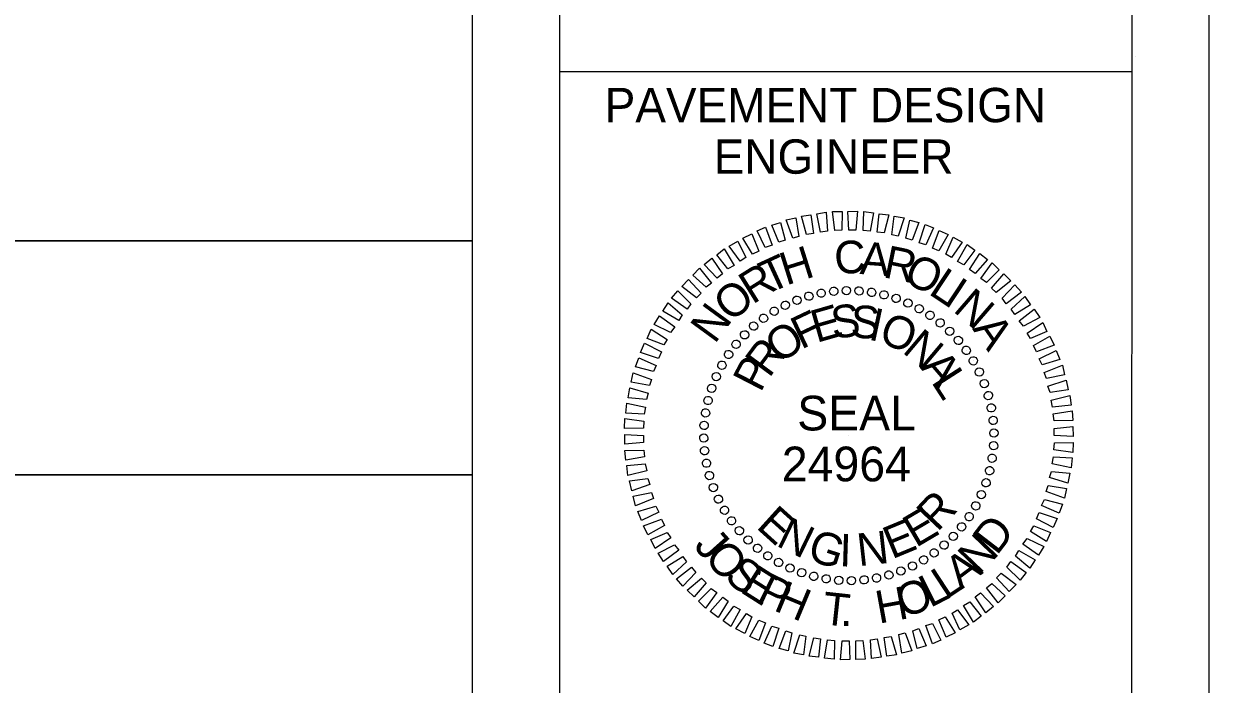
# Model space of a CAD drawing. Extents: x 1553884 to 1554215, y 810431 to 810779.
# Drawn here: x 1554125.27 to 1554156.35, y 810737.21 to 810754.53 of the extents above; entities that cross this region are included whole.
import ezdxf

# ---------------------------------------------------------------- set-up
doc = ezdxf.new("R2010")
doc.units = 0
for name, color, linetype in [('Exist Structure Minor Drop Inlet Top Elevation', 7, 'Continuous'), ('Old_Level_2', 7, 'Continuous'), ('Prop Dimension', 7, 'Continuous'), ('Prop Lane Arrow CELL', 7, 'Continuous'), ('Typical Arrow Superelevation CELL', 7, 'Continuous')]:
    doc.layers.add(name, color=color, linetype=linetype)

msp = doc.modelspace()

# ---------------------------------------------------------------- linework, layer by layer
at = {"layer": 'Exist Structure Minor Drop Inlet Top Elevation'}
for p, q in [((1554154.423, 810753.681), (1554154.423, 810753.681)), ((1554145.537, 810747.289), (1554145.537, 810747.289)), ((1554145.853, 810747.393), (1554145.853, 810747.393)), ((1554146.178, 810747.467), (1554146.178, 810747.467)), ((1554146.503, 810747.518), (1554146.503, 810747.518)), ((1554146.837, 810747.539), (1554146.837, 810747.539)), ((1554147.171, 810747.53), (1554147.171, 810747.53)), ((1554147.497, 810747.49), (1554147.497, 810747.49)), ((1554147.824, 810747.427), (1554147.824, 810747.427)), ((1554148.144, 810747.335), (1554148.144, 810747.335)), ((1554144.943, 810746.998), (1554144.943, 810746.998)), ((1554145.236, 810747.155), (1554145.236, 810747.155)), ((1554148.45, 810747.211), (1554148.45, 810747.211)), ((1554148.748, 810747.065), (1554148.748, 810747.065)), ((1554144.665, 810746.811), (1554144.665, 810746.811)), ((1554149.032, 810746.887), (1554149.032, 810746.887)), ((1554149.301, 810746.695), (1554149.301, 810746.695)), ((1554144.165, 810746.378), (1554144.165, 810746.378)), ((1554144.403, 810746.61), (1554144.403, 810746.61)), ((1554149.547, 810746.472), (1554149.547, 810746.472)), ((1554143.942, 810746.131), (1554143.942, 810746.131)), ((1554149.779, 810746.233), (1554149.779, 810746.233)), ((1554143.749, 810745.862), (1554143.749, 810745.862)), ((1554149.981, 810745.971), (1554149.981, 810745.971)), ((1554143.572, 810745.579), (1554143.572, 810745.579)), ((1554150.168, 810745.694), (1554150.168, 810745.694)), ((1554143.426, 810745.28), (1554143.426, 810745.28)), ((1554150.324, 810745.401), (1554150.324, 810745.401)), ((1554143.302, 810744.975), (1554143.302, 810744.975)), ((1554150.459, 810745.1), (1554150.459, 810745.1)), ((1554143.209, 810744.655), (1554143.209, 810744.655)), ((1554150.563, 810744.783), (1554150.563, 810744.783)), ((1554143.146, 810744.328), (1554143.146, 810744.328)), ((1554150.637, 810744.458), (1554150.637, 810744.458)), ((1554143.107, 810744.001), (1554143.107, 810744.001)), ((1554150.688, 810744.133), (1554150.688, 810744.133)), ((1554143.097, 810743.667), (1554143.097, 810743.667)), ((1554146.903, 810743.733), (1554146.903, 810743.733)), ((1554150.709, 810743.8), (1554150.709, 810743.8)), ((1554143.118, 810743.334), (1554143.118, 810743.334)), ((1554150.699, 810743.466), (1554150.699, 810743.466)), ((1554143.17, 810743.008), (1554143.17, 810743.008)), ((1554150.66, 810743.139), (1554150.66, 810743.139)), ((1554143.243, 810742.684), (1554143.243, 810742.684)), ((1554150.597, 810742.812), (1554150.597, 810742.812)), ((1554143.348, 810742.367), (1554143.348, 810742.367)), ((1554150.504, 810742.492), (1554150.504, 810742.492)), ((1554143.482, 810742.066), (1554143.482, 810742.066)), ((1554150.38, 810742.186), (1554150.38, 810742.186)), ((1554143.639, 810741.773), (1554143.639, 810741.773)), ((1554150.234, 810741.888), (1554150.234, 810741.888)), ((1554143.825, 810741.496), (1554143.825, 810741.496)), ((1554150.057, 810741.605), (1554150.057, 810741.605)), ((1554144.027, 810741.234), (1554144.027, 810741.234)), ((1554149.641, 810741.089), (1554149.641, 810741.089)), ((1554149.865, 810741.336), (1554149.865, 810741.336)), ((1554144.259, 810740.995), (1554144.259, 810740.995)), ((1554144.505, 810740.772), (1554144.505, 810740.772)), ((1554149.403, 810740.857), (1554149.403, 810740.857)), ((1554144.774, 810740.58), (1554144.774, 810740.58)), ((1554148.864, 810740.469), (1554148.864, 810740.469)), ((1554149.141, 810740.656), (1554149.141, 810740.656)), ((1554145.058, 810740.402), (1554145.058, 810740.402)), ((1554145.356, 810740.256), (1554145.356, 810740.256)), ((1554145.662, 810740.132), (1554145.662, 810740.132)), ((1554148.269, 810740.178), (1554148.269, 810740.178)), ((1554148.571, 810740.312), (1554148.571, 810740.312)), ((1554145.982, 810740.039), (1554145.982, 810740.039)), ((1554146.309, 810739.977), (1554146.309, 810739.977)), ((1554146.636, 810739.937), (1554146.636, 810739.937)), ((1554146.969, 810739.928), (1554146.969, 810739.928)), ((1554147.303, 810739.949), (1554147.303, 810739.949)), ((1554147.628, 810740), (1554147.628, 810740)), ((1554147.953, 810740.074), (1554147.953, 810740.074))]:
    msp.add_line(p, q, dxfattribs=at)
for points in [[(1554145.795, 810749.007), (1554145.658, 810749.483), (1554145.907, 810749.517), (1554145.976, 810749.033)], [(1554146.158, 810749.067), (1554146.058, 810749.543), (1554146.308, 810749.585), (1554146.339, 810749.093)], [(1554146.536, 810749.111), (1554146.475, 810749.603), (1554146.725, 810749.607), (1554146.718, 810749.114)], [(1554146.9, 810749.118), (1554146.876, 810749.61), (1554147.126, 810749.614), (1554147.082, 810749.121)], [(1554147.279, 810749.109), (1554147.293, 810749.602), (1554147.544, 810749.569), (1554147.462, 810749.089)], [(1554147.644, 810749.062), (1554147.696, 810749.549), (1554147.947, 810749.523), (1554147.827, 810749.043)], [(1554148.032, 810748.993), (1554148.092, 810749.487), (1554148.351, 810749.439), (1554148.192, 810748.958)], [(1554144.709, 810748.662), (1554144.496, 810749.098), (1554144.715, 810749.193), (1554144.89, 810748.719)], [(1554145.07, 810748.798), (1554144.881, 810749.249), (1554145.114, 810749.322), (1554145.229, 810748.853)], [(1554145.432, 810748.91), (1554145.257, 810749.385), (1554145.514, 810749.442), (1554145.591, 810748.951)], [(1554148.398, 810748.909), (1554148.496, 810749.381), (1554148.732, 810749.316), (1554148.558, 810748.858)], [(1554148.741, 810748.786), (1554148.899, 810749.266), (1554149.121, 810749.179), (1554148.924, 810748.736)], [(1554144.055, 810748.302), (1554143.76, 810748.699), (1554143.993, 810748.832), (1554144.198, 810748.396)], [(1554144.378, 810748.49), (1554144.121, 810748.91), (1554144.354, 810749.02), (1554144.544, 810748.568)], [(1554149.092, 810748.648), (1554149.266, 810749.106), (1554149.503, 810749.004), (1554149.26, 810748.575)], [(1554149.444, 810748.487), (1554149.633, 810748.93), (1554149.871, 810748.805), (1554149.59, 810748.399)], [(1554143.733, 810748.099), (1554143.438, 810748.473), (1554143.633, 810748.628), (1554143.898, 810748.193)], [(1554149.751, 810748.295), (1554150.001, 810748.739), (1554150.201, 810748.591), (1554149.919, 810748.207)], [(1554143.449, 810747.859), (1554143.109, 810748.217), (1554143.311, 810748.38), (1554143.591, 810747.968)], [(1554150.065, 810748.081), (1554150.331, 810748.503), (1554150.538, 810748.347), (1554150.211, 810747.977)], [(1554150.365, 810747.851), (1554150.661, 810748.258), (1554150.846, 810748.079), (1554150.511, 810747.747)], [(1554143.157, 810747.619), (1554142.81, 810747.939), (1554142.989, 810748.124), (1554143.299, 810747.728)], [(1554150.643, 810747.598), (1554150.962, 810747.968), (1554151.147, 810747.789), (1554150.766, 810747.479)], [(1554142.912, 810747.342), (1554142.52, 810747.638), (1554142.699, 810747.823), (1554143.031, 810747.465)], [(1554150.92, 810747.33), (1554151.255, 810747.684), (1554151.425, 810747.49), (1554151.029, 810747.188)], [(1554142.659, 810747.042), (1554142.252, 810747.33), (1554142.416, 810747.53), (1554142.763, 810747.187)], [(1554151.16, 810747.046), (1554151.518, 810747.378), (1554151.666, 810747.161), (1554151.254, 810746.903)], [(1554142.444, 810746.75), (1554142.023, 810746.993), (1554142.163, 810747.215), (1554142.533, 810746.895)], [(1554151.363, 810746.739), (1554151.759, 810747.041), (1554151.907, 810746.824), (1554151.479, 810746.597)], [(1554142.23, 810746.435), (1554141.794, 810746.647), (1554141.934, 810746.87), (1554142.341, 810746.581)], [(1554151.573, 810746.416), (1554151.985, 810746.696), (1554152.095, 810746.463), (1554151.667, 810746.274)], [(1554142.054, 810746.106), (1554141.618, 810746.28), (1554141.72, 810746.517), (1554142.142, 810746.251)], [(1554141.916, 810745.755), (1554141.443, 810745.913), (1554141.545, 810746.15), (1554141.989, 810745.923)], [(1554151.738, 810746.093), (1554152.174, 810746.336), (1554152.284, 810746.102), (1554151.817, 810745.927)], [(1554141.778, 810745.411), (1554141.305, 810745.532), (1554141.392, 810745.768), (1554141.851, 810745.571)], [(1554151.888, 810745.747), (1554152.339, 810745.959), (1554152.435, 810745.726), (1554151.967, 810745.589)], [(1554152.023, 810745.385), (1554152.498, 810745.575), (1554152.555, 810745.326), (1554152.079, 810745.227)], [(1554141.678, 810745.045), (1554141.199, 810745.128), (1554141.247, 810745.379), (1554141.728, 810745.205)], [(1554152.121, 810745.023), (1554152.596, 810745.183), (1554152.653, 810744.926), (1554152.176, 810744.864)], [(1554141.593, 810744.68), (1554141.115, 810744.724), (1554141.163, 810744.983), (1554141.644, 810744.84)], [(1554141.539, 810744.292), (1554141.054, 810744.321), (1554141.079, 810744.58), (1554141.574, 810744.475)], [(1554152.203, 810744.66), (1554152.694, 810744.782), (1554152.728, 810744.525), (1554152.244, 810744.479)], [(1554141.515, 810743.927), (1554141.023, 810743.919), (1554141.033, 810744.177), (1554141.527, 810744.11)], [(1554152.262, 810744.297), (1554152.754, 810744.382), (1554152.773, 810744.124), (1554152.281, 810744.116)], [(1554152.284, 810743.918), (1554152.776, 810743.965), (1554152.781, 810743.707), (1554152.287, 810743.736)], [(1554141.522, 810743.548), (1554141.03, 810743.502), (1554141.025, 810743.76), (1554141.519, 810743.731)], [(1554141.544, 810743.17), (1554141.052, 810743.085), (1554141.033, 810743.343), (1554141.525, 810743.351)], [(1554152.291, 810743.539), (1554152.783, 810743.548), (1554152.773, 810743.29), (1554152.279, 810743.357)], [(1554141.603, 810742.807), (1554141.112, 810742.684), (1554141.078, 810742.942), (1554141.562, 810742.988)], [(1554152.267, 810743.175), (1554152.753, 810743.145), (1554152.727, 810742.887), (1554152.232, 810742.992)], [(1554152.213, 810742.787), (1554152.691, 810742.742), (1554152.643, 810742.484), (1554152.163, 810742.627)], [(1554141.685, 810742.444), (1554141.21, 810742.284), (1554141.153, 810742.541), (1554141.63, 810742.602)], [(1554152.128, 810742.422), (1554152.607, 810742.339), (1554152.559, 810742.088), (1554152.078, 810742.262)], [(1554141.783, 810742.082), (1554141.308, 810741.892), (1554141.251, 810742.141), (1554141.727, 810742.24)], [(1554152.028, 810742.056), (1554152.501, 810741.935), (1554152.414, 810741.699), (1554151.955, 810741.895)], [(1554141.918, 810741.72), (1554141.467, 810741.508), (1554141.372, 810741.741), (1554141.839, 810741.878)], [(1554151.89, 810741.712), (1554152.363, 810741.554), (1554152.261, 810741.317), (1554151.817, 810741.544)], [(1554142.068, 810741.374), (1554141.632, 810741.131), (1554141.522, 810741.365), (1554141.989, 810741.539)], [(1554142.233, 810741.051), (1554141.821, 810740.771), (1554141.711, 810741.004), (1554142.139, 810741.193)], [(1554151.752, 810741.361), (1554152.188, 810741.187), (1554152.086, 810740.95), (1554151.664, 810741.216)], [(1554142.443, 810740.728), (1554142.047, 810740.426), (1554141.899, 810740.643), (1554142.327, 810740.87)], [(1554151.576, 810741.032), (1554152.012, 810740.82), (1554151.872, 810740.597), (1554151.465, 810740.886)], [(1554142.646, 810740.421), (1554142.288, 810740.089), (1554142.14, 810740.306), (1554142.552, 810740.564)], [(1554151.362, 810740.717), (1554151.783, 810740.474), (1554151.643, 810740.252), (1554151.273, 810740.572)], [(1554142.886, 810740.137), (1554142.551, 810739.782), (1554142.38, 810739.976), (1554142.777, 810740.279)], [(1554151.147, 810740.425), (1554151.554, 810740.137), (1554151.39, 810739.937), (1554151.043, 810740.279)], [(1554143.164, 810739.869), (1554142.844, 810739.499), (1554142.659, 810739.678), (1554143.04, 810739.988)], [(1554150.649, 810739.848), (1554150.996, 810739.528), (1554150.817, 810739.343), (1554150.507, 810739.739)], [(1554150.894, 810740.125), (1554151.286, 810739.829), (1554151.107, 810739.644), (1554150.775, 810740.002)], [(1554143.441, 810739.616), (1554143.145, 810739.209), (1554142.96, 810739.388), (1554143.295, 810739.719)], [(1554150.357, 810739.608), (1554150.697, 810739.25), (1554150.495, 810739.087), (1554150.215, 810739.499)], [(1554143.741, 810739.386), (1554143.475, 810738.964), (1554143.268, 810739.12), (1554143.595, 810739.49)], [(1554144.056, 810739.172), (1554143.805, 810738.727), (1554143.606, 810738.876), (1554143.887, 810739.26)], [(1554150.073, 810739.368), (1554150.368, 810738.994), (1554150.173, 810738.839), (1554149.908, 810739.274)], [(1554144.362, 810738.98), (1554144.173, 810738.537), (1554143.935, 810738.661), (1554144.217, 810739.068)], [(1554144.714, 810738.819), (1554144.54, 810738.361), (1554144.303, 810738.463), (1554144.546, 810738.892)], [(1554149.428, 810738.977), (1554149.685, 810738.557), (1554149.452, 810738.447), (1554149.262, 810738.899)], [(1554149.751, 810739.165), (1554150.046, 810738.768), (1554149.813, 810738.635), (1554149.608, 810739.071)], [(1554145.065, 810738.681), (1554144.907, 810738.201), (1554144.685, 810738.288), (1554144.882, 810738.731)], [(1554145.408, 810738.558), (1554145.311, 810738.086), (1554145.074, 810738.15), (1554145.248, 810738.608)], [(1554148.736, 810738.669), (1554148.925, 810738.218), (1554148.692, 810738.145), (1554148.577, 810738.613)], [(1554149.097, 810738.805), (1554149.31, 810738.369), (1554149.091, 810738.274), (1554148.916, 810738.748)], [(1554145.774, 810738.474), (1554145.714, 810737.98), (1554145.456, 810738.028), (1554145.614, 810738.509)], [(1554146.162, 810738.405), (1554146.11, 810737.918), (1554145.859, 810737.944), (1554145.98, 810738.424)], [(1554146.527, 810738.358), (1554146.513, 810737.865), (1554146.262, 810737.898), (1554146.344, 810738.377)], [(1554146.906, 810738.349), (1554146.93, 810737.857), (1554146.68, 810737.852), (1554146.724, 810738.346)], [(1554147.27, 810738.356), (1554147.331, 810737.864), (1554147.081, 810737.859), (1554147.088, 810738.352)], [(1554147.648, 810738.4), (1554147.748, 810737.924), (1554147.498, 810737.882), (1554147.467, 810738.374)], [(1554148.011, 810738.459), (1554148.148, 810737.984), (1554147.899, 810737.95), (1554147.83, 810738.434)], [(1554148.374, 810738.557), (1554148.549, 810738.082), (1554148.292, 810738.025), (1554148.215, 810738.516)]]:
    msp.add_lwpolyline(points, close=True, dxfattribs=at)
for centre, major_axis in [((1554146.505, 810747.513), (-0.011, 0.109)), ((1554146.836, 810747.533), (-0.002, 0.109)), ((1554147.168, 810747.524), (0.008, 0.109)), ((1554147.497, 810747.487), (0.017, 0.108)), ((1554145.54, 810747.281), (-0.039, 0.102)), ((1554145.854, 810747.386), (-0.03, 0.105)), ((1554146.177, 810747.464), (-0.021, 0.107)), ((1554147.823, 810747.421), (0.026, 0.106)), ((1554148.141, 810747.327), (0.036, 0.103)), ((1554148.449, 810747.205), (0.0444, 0.0997)), ((1554144.944, 810746.991), (-0.0562, 0.0936)), ((1554145.235, 810747.149), (-0.0479, 0.0981)), ((1554148.746, 810747.057), (0.0529, 0.0955)), ((1554149.029, 810746.884), (0.0611, 0.0905)), ((1554144.407, 810746.601), (-0.0716, 0.0824)), ((1554144.667, 810746.807), (-0.0642, 0.0883)), ((1554149.296, 810746.686), (0.0687, 0.0849)), ((1554144.167, 810746.372), (-0.0785, 0.0758)), ((1554149.544, 810746.466), (0.0758, 0.0785)), ((1554149.773, 810746.226), (0.0824, 0.0716)), ((1554143.947, 810746.124), (-0.0849, 0.0687)), ((1554149.979, 810745.966), (0.0883, 0.0642)), ((1554143.749, 810745.857), (-0.0905, 0.0611)), ((1554150.163, 810745.689), (0.0936, 0.0562)), ((1554143.576, 810745.574), (-0.0955, 0.0529)), ((1554150.321, 810745.398), (0.0981, 0.0479)), ((1554143.428, 810745.277), (-0.0997, 0.0444)), ((1554150.453, 810745.093), (0.102, 0.039)), ((1554143.306, 810744.969), (-0.103, 0.036)), ((1554150.558, 810744.779), (0.105, 0.03)), ((1554143.212, 810744.651), (-0.106, 0.026)), ((1554150.636, 810744.456), (0.107, 0.021)), ((1554143.146, 810744.325), (-0.108, 0.017)), ((1554150.685, 810744.128), (0.109, 0.011)), ((1554143.108, 810743.996), (-0.109, 0.008)), ((1554150.705, 810743.797), (0.109, 0.002)), ((1554143.1, 810743.664), (-0.109, -0.002)), ((1554150.697, 810743.465), (0.109, -0.008)), ((1554143.12, 810743.333), (-0.109, -0.011)), ((1554150.659, 810743.136), (0.108, -0.017)), ((1554143.169, 810743.005), (-0.107, -0.021)), ((1554150.593, 810742.81), (0.106, -0.026)), ((1554143.247, 810742.682), (-0.105, -0.03)), ((1554143.352, 810742.367), (-0.102, -0.039)), ((1554150.377, 810742.184), (0.0997, -0.0444)), ((1554150.499, 810742.492), (0.103, -0.036)), ((1554143.484, 810742.063), (-0.0981, -0.0479)), ((1554150.229, 810741.887), (0.0955, -0.0529)), ((1554143.642, 810741.772), (-0.0936, -0.0562)), ((1554150.056, 810741.604), (0.0905, -0.0611)), ((1554143.826, 810741.495), (-0.0883, -0.0642)), ((1554149.858, 810741.337), (0.0849, -0.0687)), ((1554144.032, 810741.235), (-0.0824, -0.0716)), ((1554144.261, 810740.995), (-0.0758, -0.0785)), ((1554149.638, 810741.088), (0.0785, -0.0758)), ((1554144.509, 810740.775), (-0.0687, -0.0849)), ((1554149.138, 810740.654), (0.0642, -0.0883)), ((1554149.398, 810740.86), (0.0716, -0.0824)), ((1554144.776, 810740.577), (-0.0611, -0.0905)), ((1554145.059, 810740.404), (-0.0529, -0.0955)), ((1554148.861, 810740.47), (0.0562, -0.0936)), ((1554145.356, 810740.256), (-0.0444, -0.0997)), ((1554145.664, 810740.134), (-0.036, -0.103)), ((1554145.982, 810740.04), (-0.026, -0.106)), ((1554147.951, 810740.075), (0.03, -0.105)), ((1554148.265, 810740.18), (0.039, -0.102)), ((1554148.57, 810740.312), (0.0479, -0.0981)), ((1554146.308, 810739.974), (-0.017, -0.108)), ((1554146.637, 810739.936), (-0.008, -0.109)), ((1554146.969, 810739.928), (0.002, -0.109)), ((1554147.3, 810739.948), (0.011, -0.109)), ((1554147.628, 810739.997), (0.021, -0.107))]:
    msp.add_ellipse(centre, major_axis=major_axis, ratio=0.999708, dxfattribs=at)
at = {"layer": 'Old_Level_2'}
for p, q in [((1554139.321, 810617.805), (1554139.325, 810776.052)), ((1554154.321, 810617.805), (1554154.325, 810776.052)), ((1554154.325, 810753.264), (1554139.325, 810753.264))]:
    msp.add_line(p, q, dxfattribs=at)
at = {"layer": 'Prop Dimension'}
for points in [[(1554083.164, 810748.839), (1554077.027, 810748.839), (1554077.027, 810754.977), (1554137.027, 810754.977), (1554137.027, 810748.839), (1554083.164, 810748.839), (1554083.164, 810754.977)], [(1554083.164, 810742.702), (1554077.027, 810742.702), (1554077.027, 810748.839), (1554137.027, 810748.839), (1554137.027, 810742.702), (1554083.164, 810742.702), (1554083.164, 810748.839)], [(1554083.164, 810736.565), (1554077.027, 810736.565), (1554077.027, 810742.702), (1554137.027, 810742.702), (1554137.027, 810736.565), (1554083.164, 810736.565), (1554083.164, 810742.702)]]:
    msp.add_lwpolyline(points, dxfattribs=at)
at = {"layer": 'Prop Lane Arrow CELL'}
msp.add_line((1554156.35, 810614.43), (1554156.35, 810779.427), dxfattribs=at)

# ---------------------------------------------------------------- texts
at = {"layer": 'Exist Structure Minor Drop Inlet Top Elevation'}
for s, height, rotation, p in [('C', 0.855, 2.9171, (1554146.539, 810747.964)), ('H', 0.855, 17.4535, (1554145.257, 810747.664)), ('A', 0.855, 355.649, (1554147.177, 810747.969)), ('R', 0.855, 348.3808, (1554147.77, 810747.888)), ('T', 0.855, 24.7216, (1554144.817, 810747.445)), ('O', 0.855, 333.8445, (1554148.29, 810747.78)), ('R', 0.855, 31.9898, (1554144.375, 810747.158)), ('L', 0.855, 326.5763, (1554148.962, 810747.459)), ('O', 0.855, 39.2579, (1554143.802, 810746.68)), ('I', 0.855, 326.5763, (1554149.348, 810747.204)), ('N', 0.855, 319.3082, (1554149.609, 810747.004)), ('N', 0.855, 53.7943, (1554143.385, 810746.112)), ('F', 0.855, 25.3292, (1554145.653, 810745.98)), ('E', 0.855, 15.9853, (1554146.053, 810746.158)), ('S', 0.855, 6.6414, (1554146.482, 810746.267)), ('S', 0.855, 357.2975, (1554146.935, 810746.3)), ('I', 0.855, 347.9535, (1554147.387, 810746.253)), ('O', 0.855, 338.6096, (1554147.647, 810746.197)), ('A', 0.855, 304.7718, (1554150.128, 810746.53)), ('O', 0.855, 34.6731, (1554145.089, 810745.597)), ('N', 0.855, 319.9218, (1554148.277, 810745.929)), ('R', 0.855, 53.361, (1554144.811, 810745.219)), ('P', 0.855, 62.7049, (1554144.587, 810744.838)), ('A', 0.855, 310.5779, (1554148.757, 810745.511)), ('L', 0.855, 302.7465, (1554149.046, 810745.144)), ('SEAL', 0.9096, 0, (1554145.549, 810743.865)), ('24964', 0.9099, 0, (1554145.144, 810742.531)), ('R', 0.855, 46.7271, (1554149.224, 810741.185)), ('E', 0.855, 317.8985, (1554144.446, 810741.322)), ('E', 0.855, 30.5764, (1554148.659, 810740.779)), ('N', 0.855, 334.0491, (1554144.967, 810740.854)), ('E', 0.855, 22.5011, (1554148.031, 810740.481)), ('D', 0.857, 52.4666, (1554150.78, 810740.565)), ('J', 0.857, 311.6821, (1554142.811, 810740.818)), ('G', 0.855, 342.1244, (1554145.776, 810740.486)), ('I', 0.855, 358.2751, (1554146.644, 810740.303)), ('N', 0.855, 6.3504, (1554147.162, 810740.304)), ('N', 0.857, 46.1346, (1554150.303, 810740.05)), ('O', 0.857, 311.6821, (1554143.083, 810740.512)), ('S', 0.857, 321.2064, (1554143.604, 810739.977)), ('A', 0.857, 36.5104, (1554149.83, 810739.677)), ('E', 0.857, 327.6382, (1554144.012, 810739.652)), ('L', 0.857, 33.2732, (1554149.444, 810739.419)), ('P', 0.857, 334.1252, (1554144.441, 810739.377)), ('H', 0.857, 337.3863, (1554144.9, 810739.157)), ('O', 0.857, 20.2113, (1554148.336, 810738.934)), ('L', 0.857, 26.7624, (1554149.031, 810739.207)), ('T', 0.857, 353.8166, (1554146.181, 810738.787)), ('H', 0.857, 10.3321, (1554147.687, 810738.796)), ('.', 0.857, 0.4221, (1554146.671, 810738.735))]:
    msp.add_text(s, height=height, rotation=rotation, dxfattribs=at).set_placement(p)
at = {"layer": 'Typical Arrow Superelevation CELL'}
for s, p in [('PAVEMENT DESIGN', (1554140.502, 810751.947)), ('ENGINEER', (1554143.36, 810750.597))]:
    msp.add_text(s, height=0.9, dxfattribs=at).set_placement(p)

doc.saveas('drawing.dxf')
